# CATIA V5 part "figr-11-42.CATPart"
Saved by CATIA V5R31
Part number: Part1
Bounding box of the stored display mesh (mm): x -82.6 to 82.6, y -78 to 78, z 0 to 136
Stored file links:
  D:\PROJECTS\Project 2021\US EDITION\CATIA V5 6R 2021\Resources\Part Files\c11_catia_v5_6r2021_prt\figr-11-42.CATPart
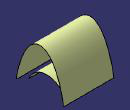
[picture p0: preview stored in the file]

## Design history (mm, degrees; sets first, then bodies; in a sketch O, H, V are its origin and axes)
Set1
  Extrude1: Element1 Sketch1, Lim1 59, Lim2 59, Direction yz-plane
  Affinity1: ToTransfor Extrude1, RatioX 1.4, RatioY 1.3, RatioZ 3.4
Body1 (main body)
  Sketch1 on yz-plane, origin (0, 0, 0), H (0, 1, 0), V (0, 0, 1)
    arc A1 centre (0, -25) radius 65 from (-60, 0) to (60, 0) cw
    point P2 (-60, 0)
    point P3 (60, 0)
    coincidence: P2 H, P3 H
